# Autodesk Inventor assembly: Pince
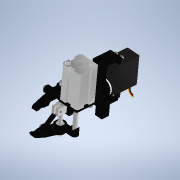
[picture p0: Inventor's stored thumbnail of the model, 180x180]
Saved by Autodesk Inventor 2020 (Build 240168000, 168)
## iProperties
Created: 2023-10
Part Number: Pince
Document SubType Name: Assembly
Designer: bruno
Mass: 175.607 g
Surface Area: 502.561 cm^2
Volume: 102.899 cm^3
Density: 1.7066 g/cm^3
Author: bruno
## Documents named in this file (7)
- C:\Users\bruno\Documents\1-Cours-2023-24\Maquettes-Inventor\Pince-robot-Dobot\Pince.iam
- C:\Users\bruno\Documents\1-Cours-2023-24\Maquettes-Inventor\Pince-robot-Dobot\Servo.iam
- C:\Users\bruno\Documents\1-Cours-2023-24\Maquettes-Inventor\Pince-robot-Dobot\pince-dr.iam
- C:\Users\bruno\Documents\1-Cours-2023-24\Maquettes-Inventor\Pince-robot-Dobot\Coulisseau.iam
- C:\Users\bruno\Documents\1-Cours-2023-24\Maquettes-Inventor\Pince-robot-Dobot\pince-ga.iam
- C:\Users\bruno\Documents\1-Cours-2023-24\Maquettes-Inventor\Pince-robot-Dobot\Axe-vertical.iam
- C:\Users\bruno\Documents\1-Cours-2023-24\Maquettes-Inventor\Pince-robot-Dobot\Bielle.iam
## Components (7 placed, 6 different names)
1. Servo:1 [sub-assembly] — Placage:1, Placage:2, Angle:1
2. pince-dr:1 [sub-assembly] — Placage:3, Placage:7, Placage:9
3. Coulisseau:1 [sub-assembly] — Placage:4, Placage:8, Placage:12
4. pince-ga:1 [sub-assembly] — Placage:5, Placage:10, Placage:11, Angle:1
5. Axe-vertical:1 [sub-assembly] — Placage:1, Placage:2, Placage:3, Placage:4, Placage:5
6. Bielle:1 [sub-assembly] — Placage:7, Placage:8, Placage:9
7. Bielle:2 [sub-assembly] — Placage:10, Placage:11, Placage:12
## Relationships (12: Mate 11, Angle 1)
- Placage:1 [Mate]: Servo:1 ↔ Axe-vertical:1
- Placage:2 [Mate]: Servo:1 ↔ Axe-vertical:1
- Placage:3 [Mate]: pince-dr:1 ↔ Axe-vertical:1
- Placage:4 [Mate]: Coulisseau:1 ↔ Axe-vertical:1
- Placage:5 [Mate]: pince-ga:1 ↔ Axe-vertical:1
- Placage:7 [Mate]: pince-dr:1 ↔ Bielle:1
- Placage:8 [Mate]: Coulisseau:1 ↔ Bielle:1
- Placage:9 [Mate]: pince-dr:1 ↔ Bielle:1
- Placage:10 [Mate]: pince-ga:1 ↔ Bielle:2
- Placage:11 [Mate]: pince-ga:1 ↔ Bielle:2
- Placage:12 [Mate]: Coulisseau:1 ↔ Bielle:2
- Angle:1: Servo:1 ↔ pince-ga:1
